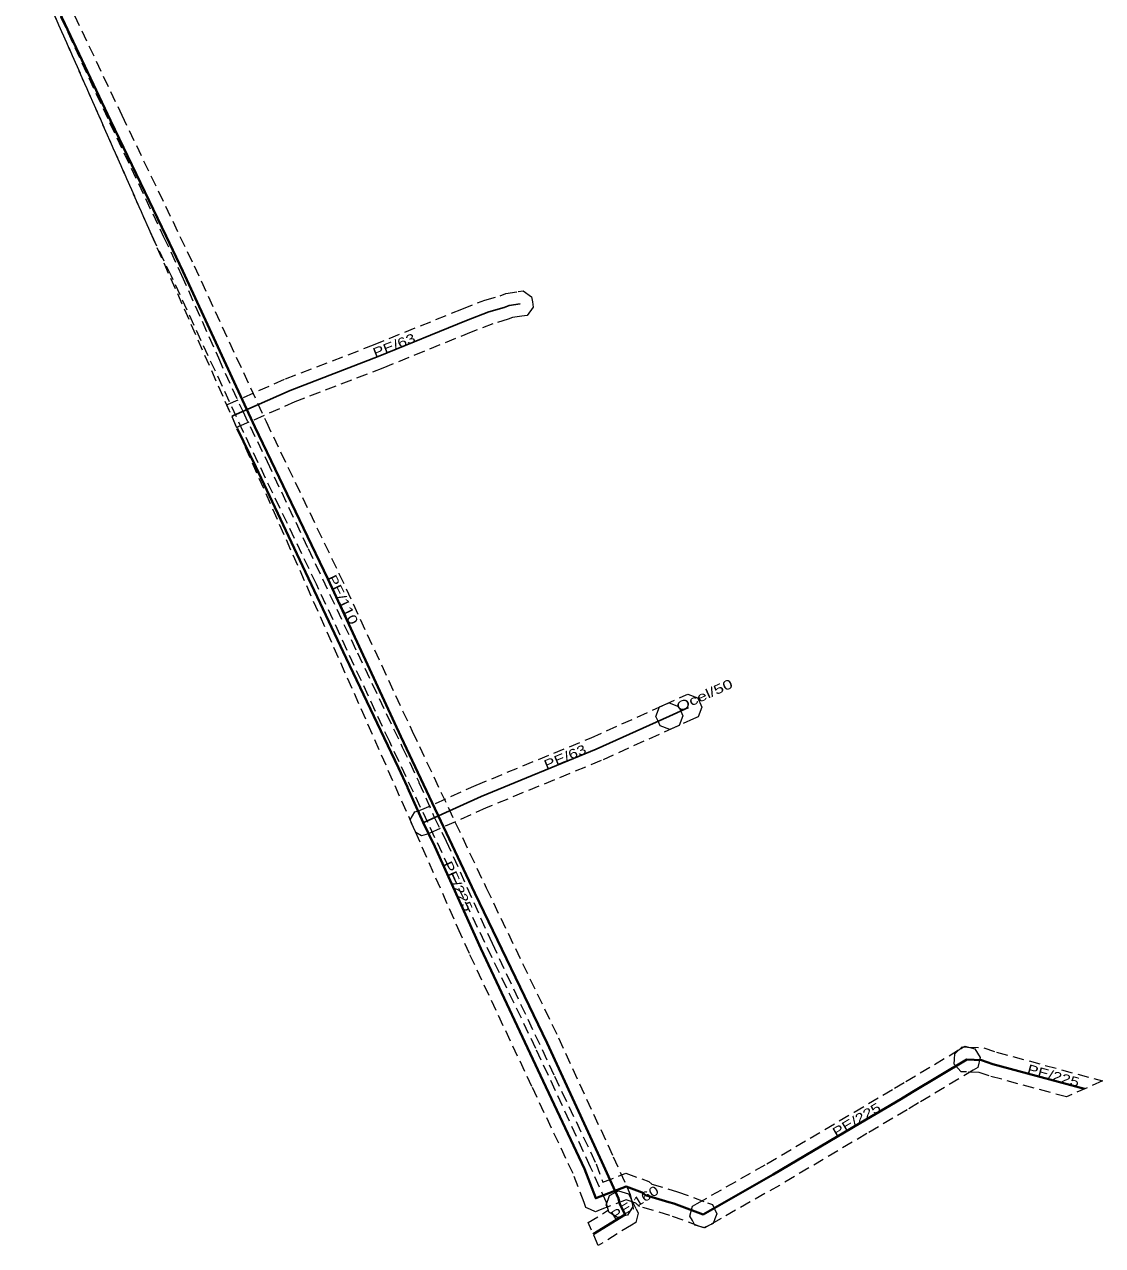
# Model space of a CAD drawing. Extents: x -469725 to -469636, y -1098908 to -1098712.
# Drawn here: x -469722.2 to -469635.6, y -1098908 to -1098809.9 of the extents above; entities that cross this region are included whole.
import ezdxf

# ---------------------------------------------------------------- set-up
doc = ezdxf.new("R2010")
doc.units = 0
doc.header["$LTSCALE"] = 0.3
doc.linetypes.add('MEDIUM_DASHED', pattern=[4.5, 3, -1.5])
for name, color, linetype, lineweight in [('1', 7, 'MEDIUM_DASHED', 13), ('14', 7, 'Continuous', 40), ('24', 7, 'Continuous', 40)]:
    doc.layers.add(name, color=color, linetype=linetype, lineweight=lineweight)
doc.layers.add('20', color=7, linetype='Continuous')
doc.layers.add('30', color=7, linetype='Continuous')

msp = doc.modelspace()

# ---------------------------------------------------------------- linework, layer by layer
at = {"layer": '1'}
for points in [[(-469718.782, -1098807.973), (-469714.401, -1098817.204), (-469708.601, -1098829.292), (-469702.816, -1098841.818), (-469696.962, -1098854.015), (-469691.078, -1098866.691), (-469685.141, -1098879.266), (-469679.332, -1098891.327), (-469674.94, -1098900.867), (-469673.573, -1098903.896), (-469673.444, -1098904.454), (-469673.35, -1098904.858), (-469673.789, -1098905.561), (-469674.192, -1098905.654), (-469674.596, -1098905.748), (-469675.299, -1098905.309), (-469675.392, -1098904.906), (-469675.477, -1098904.54), (-469676.76, -1098901.697), (-469681.142, -1098892.179), (-469686.947, -1098880.126), (-469692.89, -1098867.539), (-469698.77, -1098854.869), (-469704.626, -1098842.67), (-469710.411, -1098830.144), (-469711.996, -1098826.84), (-469722.222, -1098803.699)], [(-469719.879, -1098808.085), (-469715.384, -1098817.796), (-469711.045, -1098826.964), (-469709.6, -1098830.055), (-469706.648, -1098836.69), (-469704.695, -1098840.985), (-469702.738, -1098845.019), (-469699.446, -1098852.003), (-469695.476, -1098860.392), (-469691.878, -1098867.968), (-469691.277, -1098869.21), (-469690.551, -1098870.763), (-469690.538, -1098870.793), (-469689.304, -1098873.585), (-469688.346, -1098875.513), (-469684.671, -1098883.713), (-469679.655, -1098894.384), (-469676.319, -1098901.439), (-469675.764, -1098902.908), (-469673.912, -1098902.192), (-469672.08, -1098902.854), (-469671.843, -1098903.064), (-469669.765, -1098903.68), (-469667.365, -1098904.561), (-469666.976, -1098904.704), (-469666.629, -1098905.456), (-469666.771, -1098905.845), (-469666.914, -1098906.234), (-469667.666, -1098906.581), (-469668.055, -1098906.439), (-469670.395, -1098905.58), (-469672.837, -1098904.856), (-469673.12, -1098904.606), (-469673.888, -1098904.328), (-469675.983, -1098905.137), (-469676.371, -1098905.287), (-469676.751, -1098905.117), (-469677.131, -1098904.947), (-469677.278, -1098904.557), (-469678.161, -1098902.221), (-469681.465, -1098895.236), (-469686.489, -1098884.547), (-469687.178, -1098883.009), (-469722.152, -1098803.856)]]:
    msp.add_lwpolyline(points, dxfattribs=at)
for points in [[(-469705.132, -1098842.294), (-469705.161, -1098842.31), (-469705.972, -1098840.475), (-469705.867, -1098840.42), (-469701.265, -1098838.386), (-469694.178, -1098835.65), (-469687.087, -1098832.77), (-469685.241, -1098832.062), (-469684.028, -1098831.704), (-469683.566, -1098831.52), (-469682.571, -1098831.368), (-469682.162, -1098831.306), (-469681.495, -1098831.797), (-469681.432, -1098832.207), (-469681.37, -1098832.616), (-469681.861, -1098833.283), (-469682.271, -1098833.346), (-469683.038, -1098833.462), (-469683.372, -1098833.596), (-469684.599, -1098833.958), (-469686.353, -1098834.63), (-469693.442, -1098837.51), (-469700.501, -1098840.234), (-469704.993, -1098842.22)], [(-469690.792, -1098874.829), (-469691.245, -1098873.805), (-469690.873, -1098873.154), (-469690.474, -1098873.045), (-469690.443, -1098873.037), (-469685.94, -1098871.012), (-469676.706, -1098867.212), (-469670.835, -1098864.565), (-469670.457, -1098864.395), (-469669.682, -1098864.688), (-469669.512, -1098865.066), (-469669.342, -1098865.444), (-469669.635, -1098866.219), (-469670.013, -1098866.389), (-469675.914, -1098869.048), (-469685.15, -1098872.85), (-469689.765, -1098874.925), (-469689.946, -1098874.975), (-469690.346, -1098875.084)], [(-469671.213, -1098864.735), (-469670.835, -1098864.565), (-469669.311, -1098863.878), (-469668.933, -1098863.708), (-469668.158, -1098864.001), (-469667.988, -1098864.379), (-469667.818, -1098864.757), (-469668.111, -1098865.532), (-469668.489, -1098865.702), (-469670.013, -1098866.389), (-469670.391, -1098866.559), (-469671.166, -1098866.266), (-469671.336, -1098865.888), (-469671.506, -1098865.51)], [(-469668.565, -1098904.836), (-469668.205, -1098904.631), (-469662.592, -1098901.435), (-469655.599, -1098897.289), (-469652.341, -1098895.37), (-469651.444, -1098894.832), (-469647.043, -1098892.202), (-469646.688, -1098891.99), (-469645.884, -1098892.192), (-469645.672, -1098892.547), (-469645.46, -1098892.902), (-469645.662, -1098893.706), (-469646.017, -1098893.918), (-469650.416, -1098896.548), (-469651.319, -1098897.09), (-469654.581, -1098899.011), (-469661.588, -1098903.165), (-469667.215, -1098906.369), (-469667.575, -1098906.574), (-469668.374, -1098906.355), (-469668.579, -1098905.995), (-469668.784, -1098905.635)], [(-469644.147, -1098892.463), (-469635.638, -1098894.779), (-469638.529, -1098896.065), (-469644.733, -1098894.377), (-469645.536, -1098894.103), (-469646.572, -1098894.059), (-469646.986, -1098894.042), (-469647.546, -1098893.432), (-469647.529, -1098893.018), (-469647.512, -1098892.604), (-469646.902, -1098892.044), (-469646.488, -1098892.061), (-469645.164, -1098892.117)], [(-469673.466, -1098906.359), (-469676.134, -1098908.004), (-469676.95, -1098906.157), (-469675.304, -1098905.143), (-469675.307, -1098905.138), (-469675.497, -1098904.77), (-469675.244, -1098903.981), (-469674.876, -1098903.791), (-469674.508, -1098903.601), (-469673.719, -1098903.854), (-469673.529, -1098904.222), (-469673.102, -1098905.05), (-469672.923, -1098905.398), (-469673.133, -1098906.153)]]:
    msp.add_lwpolyline(points, close=True, dxfattribs=at)
at = {"layer": '14', "lineweight": 25}
msp.add_line((-469670.424, -1098865.477), (-469668.9, -1098864.79), dxfattribs=at)
for points in [[(-469705.567, -1098841.392), (-469705.43, -1098841.32), (-469700.883, -1098839.31), (-469693.81, -1098836.58), (-469686.72, -1098833.7), (-469684.92, -1098833.01), (-469683.699, -1098832.649), (-469683.302, -1098832.491), (-469682.421, -1098832.357)], [(-469690.21, -1098874.01), (-469690.104, -1098873.981), (-469685.545, -1098871.931), (-469676.31, -1098868.13), (-469670.424, -1098865.477)]]:
    msp.add_lwpolyline(points, dxfattribs=at)
at = {"layer": '14'}
for points in [[(-469667.71, -1098905.5), (-469670.08, -1098904.63), (-469670.462, -1098904.516), (-469672.34, -1098903.96), (-469672.6, -1098903.73), (-469673.9, -1098903.26), (-469676.343, -1098904.204), (-469677.24, -1098901.83), (-469680.56, -1098894.81), (-469685.58, -1098884.13), (-469689.25, -1098875.94), (-469690.21, -1098874.01), (-469691.451, -1098871.2), (-469691.46, -1098871.18), (-469692.18, -1098869.64), (-469692.78, -1098868.4), (-469696.38, -1098860.82), (-469700.35, -1098852.43), (-469703.64, -1098845.45), (-469705.137, -1098842.364)], [(-469667.71, -1098905.5), (-469662.09, -1098902.3), (-469655.09, -1098898.15), (-469651.83, -1098896.23), (-469650.93, -1098895.69), (-469646.53, -1098893.06)], [(-469646.53, -1098893.06), (-469645.35, -1098893.11), (-469644.44, -1098893.42), (-469637.083, -1098895.422)]]:
    msp.add_lwpolyline(points, dxfattribs=at)
at = {"layer": '24'}
for points in [[(-469674.418, -1098904.68), (-469674.525, -1098904.218), (-469675.85, -1098901.282), (-469680.237, -1098891.753), (-469686.044, -1098879.696), (-469691.984, -1098867.115), (-469697.866, -1098854.442), (-469703.721, -1098842.244), (-469709.506, -1098829.718), (-469710.849, -1098826.917), (-469715.304, -1098817.635), (-469719.685, -1098808.402), (-469720.971, -1098805.692), (-469721.585, -1098804.476), (-469721.376, -1098804.338)], [(-469676.542, -1098907.08), (-469673.991, -1098905.508), (-469674.418, -1098904.68)]]:
    msp.add_lwpolyline(points, dxfattribs=at)

# ---------------------------------------------------------------- texts
at = {"layer": '20'}
for s, rotation, width, p in [('PE/63', 21.105, 1.3, (-469694.06, -1098836.676)), ('Ocel/50', 24.265, 1.4, (-469669.662, -1098865.133)), ('PE/63', 22.371, 1.3, (-469680.305, -1098869.774)), ('PE/225', 294.138, 1.3, (-469688.624, -1098877.337)), ('PE/225', 344.777, 1.3, (-469641.747, -1098894.153)), ('PE/225', 30.662, 1.3, (-469657.045, -1098899.309))]:
    msp.add_text(s, height=0.75, rotation=rotation, dxfattribs=dict(at, width=width)).set_placement(p)
at = {"layer": '30', "width": 1.3}
for s, rotation, p in [('PE/110', 295.641, (-469697.911, -1098854.347)), ('PE/160', 31.648, (-469674.828, -1098906.023))]:
    msp.add_text(s, height=0.75, rotation=rotation, dxfattribs=at).set_placement(p)

doc.saveas('drawing.dxf')
